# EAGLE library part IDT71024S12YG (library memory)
MEMORY
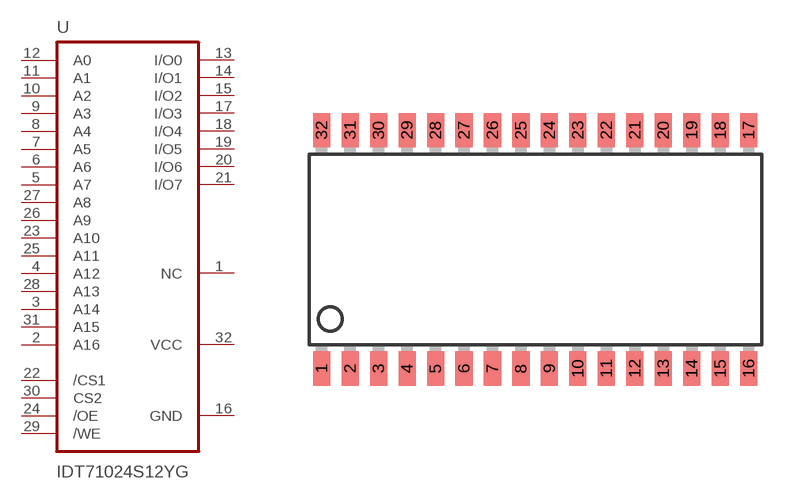
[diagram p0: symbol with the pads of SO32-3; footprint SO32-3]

Designator prefix U

## IDT71024S12YG  [SO32-3]
1  NC  nc
2  A16  in
3  A14  in
4  A12  in
5  A7  in
6  A6  in
7  A5  in
8  A4  in
9  A3  in
10  A2  in
11  A1  in
12  A0  in
13  I/O0
14  I/O1
15  I/O2
16  GND  pwr
17  I/O3
18  I/O4
19  I/O5
20  I/O6
21  I/O7
22  /CS1  in
23  A10  in
24  /OE  in
25  A11  in
26  A9  in
27  A8  in
28  A13  in
29  /WE  in
30  CS2  in
31  A15  in
32  VCC  pwr

## Footprint SO32-3 (pad centres in mm)
Small Outline Package
smd 0.762 x 1.524: 1 -9.525,-5.315; 2 -8.255,-5.315; 3 -6.985,-5.315; 4 -5.715,-5.315; 5 -4.445,-5.315; 6 -3.175,-5.315; 7 -1.905,-5.315; 8 -0.635,-5.315; 9 0.635,-5.315; 10 1.905,-5.315; 11 3.175,-5.315; 12 4.445,-5.315; 13 5.715,-5.315; 14 6.985,-5.315; 15 8.255,-5.315; 16 9.525,-5.315; 17 9.525,5.315; 18 8.255,5.315; 19 6.985,5.315; 20 5.715,5.315; 21 4.445,5.315; 22 3.175,5.315; 23 1.905,5.315; 24 0.635,5.315; 25 -0.635,5.315; 26 -1.905,5.315; 27 -3.175,5.315; 28 -4.445,5.315; 29 -5.715,5.315; 30 -6.985,5.315; 31 -8.255,5.315; 32 -9.525,5.315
